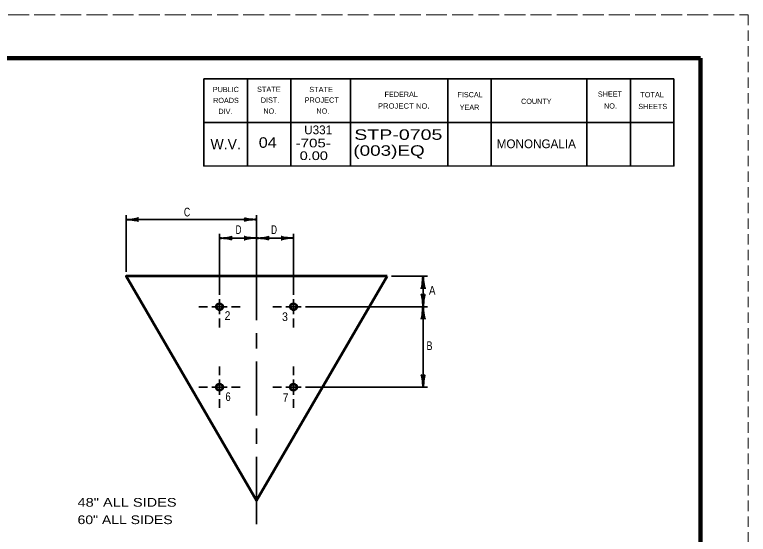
# Model space of a CAD drawing. Extents: x -68 to 613, y -1036 to -595.
# Drawn here: x 444 to 612.5, y -714.8 to -595.5 of the extents above; entities that cross this region are included whole.
import ezdxf
from ezdxf.enums import TextEntityAlignment as Align

# ---------------------------------------------------------------- set-up
doc = ezdxf.new("R2010")
doc.units = 0
doc.header["$LTSCALE"] = 0.8
doc.linetypes.add('LONG_DASHED', pattern=[7.5, 6, -1.5])
doc.linetypes.add('MEDIUM_DASHED', pattern=[4.5, 3, -1.5])
doc.layers.add('1', color=7, linetype='Continuous', lineweight=53)
doc.layers.add('61', color=7, linetype='Continuous', lineweight=35)

msp = doc.modelspace()

# ---------------------------------------------------------------- linework, layer by layer
at = {"layer": '1', "linetype": 'MEDIUM_DASHED', "lineweight": 13}
msp.add_line((612.5175, -595.4958), (612.4975, -1035.5158), dxfattribs=at)
at = {"layer": '1', "lineweight": 35}
for p, q in [((469.5613, -654.5509), (469.5613, -641.5509)), ((499.5613, -665.6297), (499.5613, -641.5509)), ((469.5613, -642.5509), (499.5613, -642.5509)), ((491.0613, -659.8009), (491.0613, -645.8009)), ((508.0613, -659.8009), (508.0613, -645.8009)), ((530.5613, -655.5509), (538.8113, -655.5509)), ((491.0613, -660.8009), (491.0613, -664.3009)), ((508.0613, -660.8009), (508.0613, -664.3009)), ((488.3113, -662.5509), (486.3113, -662.5509)), ((492.8113, -662.5509), (489.3113, -662.5509)), ((493.8113, -662.5509), (495.8113, -662.5509)), ((505.3113, -662.5509), (503.3113, -662.5509)), ((509.8113, -662.5509), (506.3113, -662.5509)), ((510.8113, -662.5509), (538.8113, -662.5509)), ((491.0613, -665.3009), (491.0613, -667.3009)), ((508.0613, -665.3009), (508.0613, -667.3009)), ((499.5613, -672.1297), (499.5613, -668.6297)), ((499.5613, -687.5509), (499.5613, -675.1297)), ((491.0613, -678.3009), (491.0613, -676.3009)), ((508.0613, -678.3009), (508.0613, -676.3009)), ((491.0613, -679.3009), (491.0613, -682.8009)), ((508.0613, -679.3009), (508.0613, -682.8009)), ((488.3113, -681.0509), (486.3113, -681.0509)), ((492.8113, -681.0509), (489.3113, -681.0509)), ((493.8113, -681.0509), (495.8113, -681.0509)), ((505.3113, -681.0509), (503.3113, -681.0509)), ((509.8113, -681.0509), (506.3113, -681.0509)), ((510.8113, -681.0509), (538.8113, -681.0509)), ((491.0613, -683.8009), (491.0613, -685.8009)), ((508.0613, -683.8009), (508.0613, -685.8009)), ((499.5613, -694.0509), (499.5613, -690.5509)), ((499.5613, -697.0509), (499.5613, -712.4792))]:
    msp.add_line(p, q, dxfattribs=at)
at = {"layer": '1'}
msp.add_line((529.5613, -655.5509), (499.5613, -707.0509), dxfattribs=at)
at = {"layer": '1', "lineweight": 35}
for points in [[(491.0613, -646.8009), (499.5613, -646.8009), (508.0613, -646.8009)], [(537.8113, -655.5509), (537.8113, -662.5509), (537.8113, -681.0509)]]:
    msp.add_lwpolyline(points, dxfattribs=at)
at = {"layer": '1'}
msp.add_lwpolyline([(529.5613, -655.5509), (469.5613, -655.5509), (499.5613, -707.0509)], dxfattribs=at)
for centre in [(491.0613, -662.5509), (508.0613, -662.5509), (491.0613, -681.0509), (508.0613, -681.0509)]:
    msp.add_circle(centre, 0.75, dxfattribs=at)
at = {"layer": '1', "lineweight": 40}
for centre, major_axis, ratio, start_param, end_param in [((470.6818, -642.7625), (-1.7565, 0.1757), 0.07063, 3.14071475, 5.41810995), ((470.6818, -642.7625), (-1.7565, 0.1757), 0.07063, 3.14071475, 5.41810995), ((470.6525, -642.2746), (-1.7857, -0.1562), 0.122415, 0.89635335, 3.14159265), ((470.6525, -642.2746), (-1.7857, -0.1562), 0.122415, 0.89635335, 3.14159265), ((498.4701, -642.8272), (1.7857, 0.1562), 0.122415, 0.89635335, 3.14159265), ((498.4701, -642.8272), (1.7857, 0.1562), 0.122415, 0.89635335, 3.14159265), ((498.4408, -642.3393), (1.7565, -0.1757), 0.07063, 3.14071475, 5.41810995), ((498.4408, -642.3393), (1.7565, -0.1757), 0.07063, 3.14071475, 5.41810995), ((492.1818, -647.0125), (-1.7565, 0.1757), 0.07063, 3.14071475, 5.41810995), ((492.1818, -647.0125), (-1.7565, 0.1757), 0.07063, 3.14071475, 5.41810995), ((492.1525, -646.5246), (-1.7857, -0.1562), 0.122415, 0.89635335, 3.14159265), ((492.1525, -646.5246), (-1.7857, -0.1562), 0.122415, 0.89635335, 3.14159265), ((498.4701, -647.0772), (1.7857, 0.1562), 0.122415, 0.89635335, 3.14159265), ((498.4701, -647.0772), (1.7857, 0.1562), 0.122415, 0.89635335, 3.14159265), ((498.4408, -646.5893), (1.7565, -0.1757), 0.07063, 3.14071475, 5.41810995), ((498.4408, -646.5893), (1.7565, -0.1757), 0.07063, 3.14071475, 5.41810995), ((500.6818, -647.0125), (-1.7565, 0.1757), 0.07063, 3.14071475, 5.41810995), ((500.6818, -647.0125), (-1.7565, 0.1757), 0.07063, 3.14071475, 5.41810995), ((500.6525, -646.5246), (-1.7857, -0.1562), 0.122415, 0.89635335, 3.14159265), ((500.6525, -646.5246), (-1.7857, -0.1562), 0.122415, 0.89635335, 3.14159265), ((506.9701, -647.0772), (1.7857, 0.1562), 0.122415, 0.89635335, 3.14159265), ((506.9408, -646.5893), (1.7565, -0.1757), 0.07063, 3.14071475, 5.41810995), ((537.5997, -656.6714), (0.1757, 1.7565), 0.07063, 3.14071475, 5.41810995), ((537.5997, -656.6714), (0.1757, 1.7565), 0.07063, 3.14071475, 5.41810995), ((538.0876, -656.6421), (-0.1562, 1.7857), 0.122415, 0.89635335, 3.14159265), ((538.0876, -656.6421), (-0.1562, 1.7857), 0.122415, 0.89635335, 3.14159265), ((537.535, -661.4597), (0.1562, -1.7857), 0.122415, 0.89635335, 3.14159265), ((537.535, -661.4597), (0.1562, -1.7857), 0.122415, 0.89635335, 3.14159265), ((538.0229, -661.4304), (-0.1757, -1.7565), 0.07063, 3.14071475, 5.41810995), ((538.0229, -661.4304), (-0.1757, -1.7565), 0.07063, 3.14071475, 5.41810995), ((537.5997, -663.6714), (0.1757, 1.7565), 0.07063, 3.14071475, 5.41810995), ((537.5997, -663.6714), (0.1757, 1.7565), 0.07063, 3.14071475, 5.41810995), ((538.0876, -663.6421), (-0.1562, 1.7857), 0.122415, 0.89635335, 3.14159265), ((538.0876, -663.6421), (-0.1562, 1.7857), 0.122415, 0.89635335, 3.14159265), ((537.535, -679.9597), (0.1562, -1.7857), 0.122415, 0.89635335, 3.14159265), ((538.0229, -679.9304), (-0.1757, -1.7565), 0.07063, 3.14071475, 5.41810995)]:
    msp.add_ellipse(centre, major_axis=major_axis, ratio=ratio, start_param=start_param, end_param=end_param, dxfattribs=at)
at = {"layer": '61', "linetype": 'LONG_DASHED', "lineweight": 13}
msp.add_line((-67.5025, -595.4958), (612.5175, -595.4958), dxfattribs=at)
at = {"layer": '61', "lineweight": 158}
msp.add_line((601.5375, -605.4958), (601.5575, -1025.5358), dxfattribs=at)
at = {"layer": '61'}
for p, q in [((497.4575, -610.2558), (497.4575, -630.2558)), ((507.4575, -610.2558), (507.4575, -630.2558)), ((521.1375, -610.2558), (521.1375, -630.2558)), ((543.4575, -610.2558), (543.4575, -630.2558)), ((553.4575, -610.2558), (553.4575, -630.2558)), ((575.4375, -610.2358), (575.4375, -630.2358)), ((585.4375, -610.2358), (585.4375, -630.2358)), ((595.4575, -620.2758), (487.4375, -620.2558))]:
    msp.add_line(p, q, dxfattribs=at)
at = {"layer": '61', "lineweight": 158}
msp.add_lwpolyline([(601.5375, -605.4958), (-37.5025, -605.4958), (-37.5025, -1025.5158)], dxfattribs=at)
at = {"layer": '61'}
for points in [[(595.4375, -610.2358), (487.4575, -610.2558), (487.4575, -630.2558)], [(595.4375, -610.2358), (595.4375, -630.2358), (487.4575, -630.2558)]]:
    msp.add_lwpolyline(points, dxfattribs=at)

# ---------------------------------------------------------------- texts
at = {"layer": '1'}
for s, width, p in [('C', 0.75, (483.5775, -641.8288)), ('D', 0.7, (495.3965, -645.8535)), ('D', 0.7, (503.569, -645.8535)), ('A', 0.85, (539.9059, -659.8144)), ('2', 0.9, (492.8818, -665.6)), ('3', 0.9, (506.0837, -665.8516)), ('B', 0.75, (539.2772, -672.5176)), ('6', 0.8, (493.0075, -684.2145)), ('7', 0.9, (506.2094, -684.4661))]:
    msp.add_text(s, height=2, dxfattribs=dict(at, width=width)).set_placement(p, align=Align.CENTER)
for s, width, p in [('48" ALL SIDES', 1.25, (458.4309, -708.4827)), ('60" ALL SIDES', 1.2, (458.4309, -712.4827))]:
    msp.add_text(s, height=2, dxfattribs=dict(at, width=width)).set_placement(p)
at = {"layer": '61'}
for s, height, rotation, p in [('PUBLIC', 1.201, 0.033, (489.4975, -613.2758)), ('FEDERAL', 1.201, 0.007, (528.9575, -614.3958)), ('FISCAL', 1.201, 359.942, (545.6975, -614.4558)), ('SHEET', 1.201, 0.059, (577.9575, -614.3358)), ('ROADS', 1.201, 0.124, (489.5775, -615.7958)), ('DIST.', 1.201, 0.056, (500.5375, -615.7158)), ('COUNTY', 1.201, 0.069, (560.3175, -615.9958)), ('YEAR', 1.201, 0.105, (546.2175, -617.3558)), ('SHEETS', 1.201, 359.959, (587.2375, -617.1758)), ('DIV.', 1.201, 359.932, (490.7775, -618.2958)), ('U331', 2.007, 0.054, (510.4975, -622.9558)), ('W.V.', 2.401, 0.029, (488.9737, -626.4426)), ('MONONGALIA', 2.007, 0.009, (554.7175, -626.1558))]:
    msp.add_text(s, height=height, rotation=rotation, dxfattribs=at).set_placement(p)
for s, height, rotation, width, p in [('STATE', 1.201, 0.059, 1.05, (499.6575, -613.2158)), ('STATE', 1.201, 0.059, 1.05, (511.6575, -613.2758)), ('TOTAL', 1.201, 359.926, 1.05, (587.6975, -614.4758)), ('PROJECT', 1.201, 359.908, 1.05, (510.5775, -615.6958)), ('PROJECT NO.', 1.201, 359.922, 1.1, (527.4175, -617.0558)), ('NO.', 1.201, 359.852, 0.95, (579.3775, -617.0558)), ('NO.', 1.201, 359.852, 0.95, (501.1175, -618.2358)), ('NO.', 1.201, 0.225, 0.95, (513.3175, -618.2358)), ('  STP-0705 ', 2.401, 0.012, 1.4, (519.4975, -624.2358)), ('04', 2.401, 0.029, 1.15, (500.0575, -626.0558)), (' -705- ', 1.99, 0.065, 1.3, (507.5775, -625.9758)), (' 0.00 ', 1.99, 359.958, 1.25, (508.5375, -628.8758)), ('  (003)EQ  ', 2.401, 0.012, 1.35, (519.3775, -627.8958))]:
    msp.add_text(s, height=height, rotation=rotation, dxfattribs=dict(at, width=width)).set_placement(p)

doc.saveas('drawing.dxf')
